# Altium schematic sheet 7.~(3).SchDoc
size 420 x 297 mm
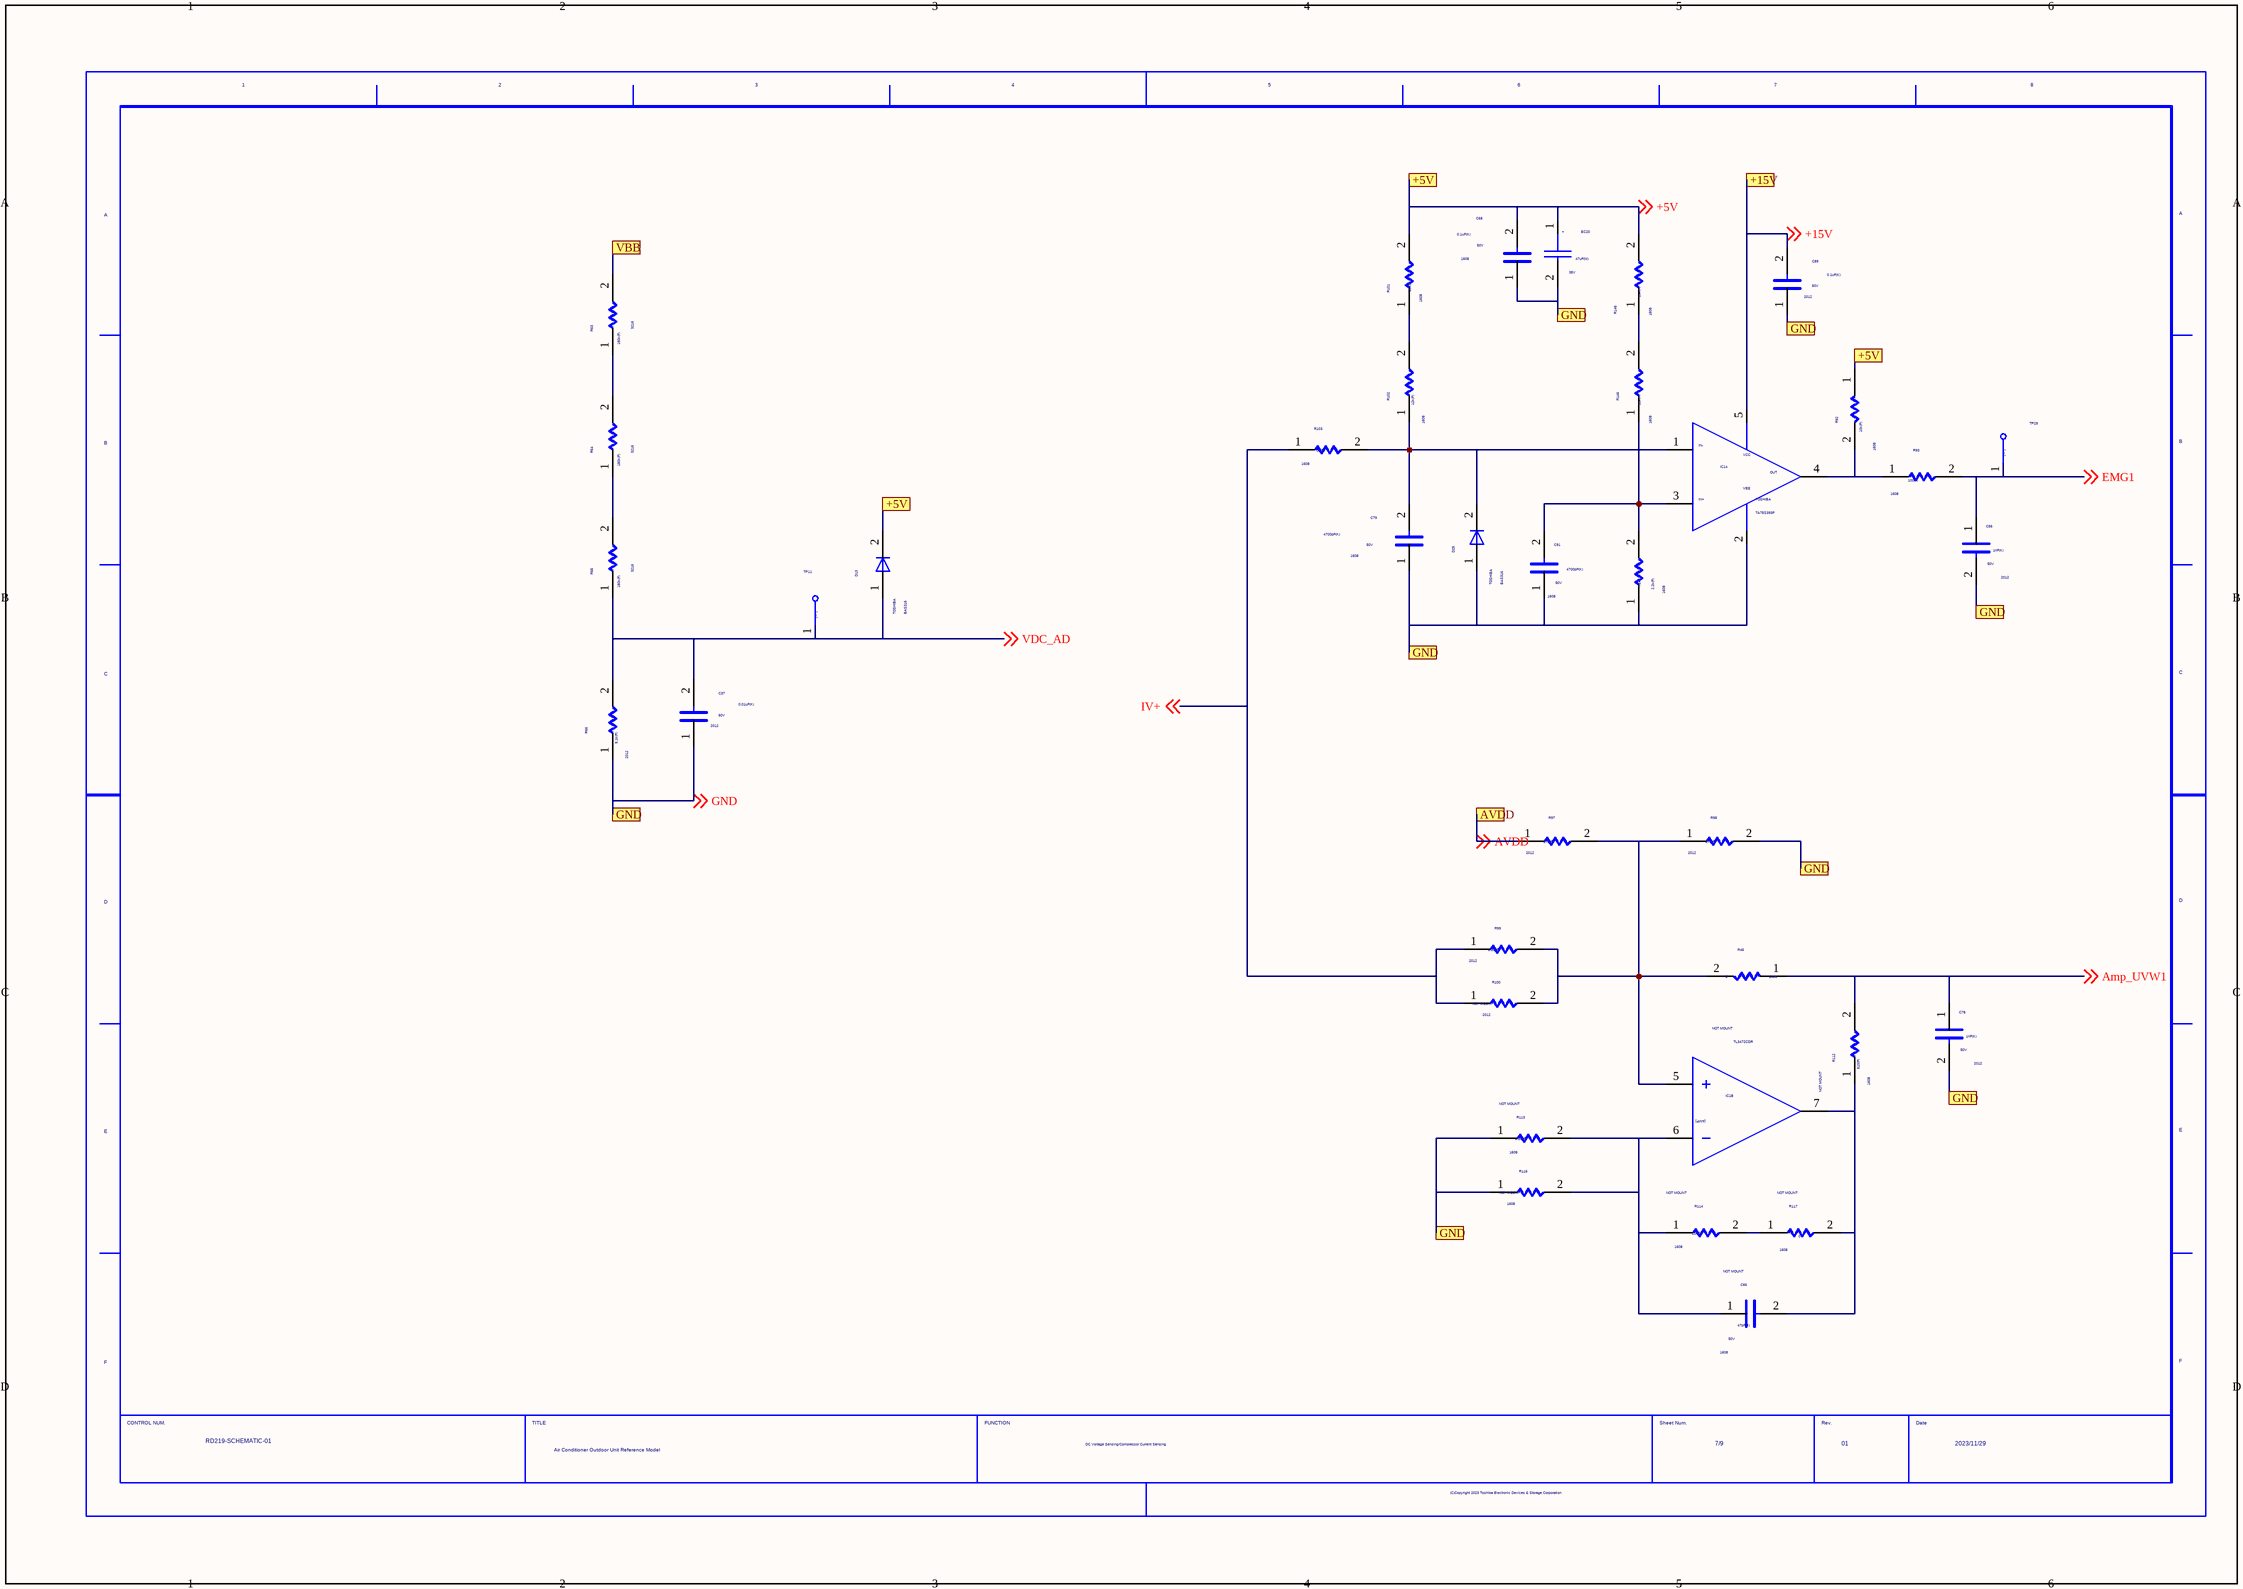
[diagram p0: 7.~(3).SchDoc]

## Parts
C37  SIZECODESMD: 2012  VAL2: 50V  VAL1: 0.01uF(K)  (hidden comment: C)
C56  VAL2: 50V  SIZECODESMD: 2012  VAL1: 1nF(K)  (hidden comment: C)
C66  NOTMOUNT: NOT MOUNT  VAL2: 50V  SIZECODESMD: 1608  VAL1: 47pF(J)  (hidden comment: C)
C68  VAL2: 50V  SIZECODESMD: 1608  VAL1: 0.1uF(K)  (hidden comment: C)
C78  VAL2: 50V  SIZECODESMD: 2012  VAL1: 1nF(K)  (hidden comment: C)
C79  VAL2: 50V  SIZECODESMD: 1608  VAL1: 4700pF(K)  (hidden comment: C)
C89  VAL2: 50V  SIZECODESMD: 2012  VAL1: 0.1uF(K)  (hidden comment: C)
C91  VAL2: 50V  SIZECODESMD: 1608  VAL1: 4700pF(K)  (hidden comment: C)
D13  USERCOMPTEXT3: TOSHIBA  VAL3: BAS316  (hidden comment: D_CUSTOM)
D25  USERCOMPTEXT3: TOSHIBA  VAL3: BAS316  (hidden comment: D_CUSTOM)
EC20  VAL2: 35V  VAL1: 47uF(M)  (hidden comment: EC)
IC1  NOTMOUNT: NOT MOUNT  VAL3: TL3472CDR  (hidden comment: AMP_1)  (part B of 2)
IC14  USERCOMPTEXT3: TOSHIBA  (hidden comment: TA75S393F)
R45  SIZECODESMD: 1608  VAL1: 0  (hidden comment: R)
R63  SIZECODESMD: 3216  VAL1: 180k(F)  (hidden comment: R)
R64  SIZECODESMD: 3216  VAL1: 180k(F)  (hidden comment: R)
R65  SIZECODESMD: 3216  VAL1: 180k(F)  (hidden comment: R)
R66  VAL1: 5.1k(F)  SIZECODESMD: 2012  (hidden comment: R)
R92  SIZECODESMD: 1608  VAL1: 10k(F)  (hidden comment: R)
R93  SIZECODESMD: 1608  VAL1: 100(F)  (hidden comment: R)
R97  SIZECODESMD: 2012  VAL1: 27k(F)  (hidden comment: R)
R98  SIZECODESMD: 2012  VAL1: 27k(F)  (hidden comment: R)
R99  SIZECODESMD: 2012  VAL1: 1.2k(F)  (hidden comment: R)
R100  SIZECODESMD: 2012  NOTMOUNT: NOT MOUNT  (hidden comment: R)
R101  SIZECODESMD: 1608  VAL1: 20k(F)  (hidden comment: R)
R102  SIZECODESMD: 1608  VAL1: 12k(F)  (hidden comment: R)
R103  SIZECODESMD: 1608  VAL1: 2k(F)  (hidden comment: R)
R112  NOTMOUNT: NOT MOUNT  SIZECODESMD: 1608  VAL1: 510(F)  (hidden comment: R)
R113  NOTMOUNT: NOT MOUNT  SIZECODESMD: 1608  VAL1: 1.1k(F)  (hidden comment: R)
R114  NOTMOUNT: NOT MOUNT  SIZECODESMD: 1608  VAL1: 12k(F)  (hidden comment: R)
R116  SIZECODESMD: 1608  NOTMOUNT: NOT MOUNT  (hidden comment: R)
R117  NOTMOUNT: NOT MOUNT  SIZECODESMD: 1608  VAL1: 0  (hidden comment: R)
R145  SIZECODESMD: 1608  VAL1: 10k(F)  (hidden comment: R)
R146  SIZECODESMD: 1608  VAL1: 12k(F)  (hidden comment: R)
R147  SIZECODESMD: 1608  VAL1: 2.2k(F)  (hidden comment: R)
TP11  TP  (value not drawn)
TP29  TP  (value not drawn)
U?  DATE: 2023/11/29  TITLE: Air Conditioner Outdoor Unit / Reference Model  FUNCTION: DC Voltage Sensing/Compressor Current Sensing  DRAWINGNUMBER: RD219-SCHEMATIC-01  SHEETNUMBER: 7/9  REVISION: 01  (hidden comment: WAKU_DEF100)

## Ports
+5V, +15V, AVDD, GND, VBB

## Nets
+5V: C68.2 D13.2 EC20.1 R92.1 R101.2 R145.2 ; off-sheet +5V, port +5V
+15V: C89.2 IC14.5 ; off-sheet +15V, port +15V
Amp_UVW1: C78.1 R45.1 R112.2 ; off-sheet Amp_UVW1
AVDD: R97.1 ; off-sheet AVDD, port AVDD
EMG1: C56.1 R93.2 TP29.1 ; off-sheet EMG1
GND: C37.1 C56.2 C68.1 C78.2 C79.1 C89.1 C91.1 D25.1 EC20.2 IC14.2 R66.1 R98.2 R113.1 R116.1 R147.1 ; off-sheet GND, port GND
IV+: R99.1 R100.1 R103.1 ; off-sheet IV+
NetC66_1: C66.1 IC1.6 R113.2 R114.1 R116.2
NetC66_2: C66.2 IC1.7 R112.1 R117.2
NetC79_2: C79.2 D25.2 IC14.1 R102.1 R103.2
NetC91_2: C91.2 IC14.3 R146.1 R147.2
NetIC1_5: IC1.5 R45.2 R97.2 R98.1 R99.2 R100.2
NetIC14_4: IC14.4 R92.2 R93.1
NetR63_1: R63.1 R64.2
NetR64_1: R64.1 R65.2
NetR101_1: R101.1 R102.2
NetR114_2: R114.2 R117.1
NetR145_1: R145.1 R146.2
VBB: R63.2 ; port VBB
VDC_AD: C37.2 D13.1 R65.1 R66.2 TP11.1 ; off-sheet VDC_AD

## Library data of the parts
C37 = C: OriginalSymbolOrigin: (2540,7620); VAL3: AC0805KRX7R9BB103
C56 C78 = C: OriginalSymbolOrigin: (2540,7620); COMP: AC0805KRX7R9BB102
C66 = C: OriginalSymbolOrigin: (2540,7620); COMP: AC0603JRNPO9BN470
C68 C89 = C: OriginalSymbolOrigin: (2540,7620); COMP: AC0603KRX7R9BB104
C79 C91 = C: OriginalSymbolOrigin: (2540,7620); COMP: AC0603KRX7R9BB472
D13 D25 = D_CUSTOM: SAVEAREA0: -1668,-97,14265,7829; SAVECOUNT: 4; TIME: 14:49:55; UPDATEUSER: w20165dm; UPDATETIME: 16:47:49; OriginalSymbolOrigin: (5080,5080)
EC20 = EC: SAVEAREA0: -1432,-1528,20311,14389; SAVECOUNT: 53; TIME: 15:02:55; UPDATEUSER: w20165dm; UPDATETIME: 16:35:05; OriginalSymbolOrigin: (2540,10160); VAL3: CS1V470M_CRE54
IC1 = AMP_1: SAVEAREA0: -6226,-235,36343,20943; TIME: 17:09:52; UPDATEUSER: w20165dm; SAVECOUNT: 1; OriginalSymbolOrigin: (5080,20320); CaptureCellPackProp: AMP_1B; FUNCN: IC1_2
IC14 = TA75S393F: SAVECOUNT: 22; SAVEAREA0: -11585,-294,41625,26178; TIME: 20:02:00; UPDATEUSER: w20165dm; UPDATETIME: 20:02:39; OriginalSymbolOrigin: (5080,22860)
R45 = R: OriginalSymbolOrigin: (5080,5080); COMP: AC0603FR_070RL; VAL3: AC0603FR-070RL; VAL2: 100mW
R63-R65 = R: OriginalSymbolOrigin: (5080,5080); VAL3: AC1206FR-07180KL; VAL2: 250mW; COMP: AC1206FR_07180KL
R66 = R: OriginalSymbolOrigin: (5080,5080); VAL3: AC0805FR-075K1L; VAL2: 125mW; COMP: AC0805FR_075K1L
R92 = R_Dup1: OriginalSymbolOrigin: (5080,5080); VAL2: 100mW; VAL3: AC0603FR_0710KL
R93 = R: OriginalSymbolOrigin: (5080,5080); COMP: AC0603FR_07100RL; VAL2: 100mW
R97 R98 = R: OriginalSymbolOrigin: (5080,5080); COMP: AC0805FR_0727KL; VAL2: 125mW
R99 = R: OriginalSymbolOrigin: (5080,5080); COMP: AC0805FR_071K2L; VAL2: 125mW
R100 = R: OriginalSymbolOrigin: (5080,5080); COMP: SMT_0805_R; VAL3: NC
R101 = R_Dup1: OriginalSymbolOrigin: (5080,5080); VAL3: AC0603FR_0720KL; VAL2: 100mW
R102 R146 = R_Dup1: OriginalSymbolOrigin: (5080,5080); VAL3: AC0603FR_0712KL; VAL2: 100mW
R103 = R: OriginalSymbolOrigin: (5080,5080); COMP: AC0603FR_072KL; VAL2: 100mW
R112 = R_Dup1: OriginalSymbolOrigin: (5080,5080); VAL2: 100mW; VAL3: AC0603FR_07510RL
R113 = R: OriginalSymbolOrigin: (5080,5080); COMP: AC0603FR_071K1L; VAL2: 100mW
R114 = R: OriginalSymbolOrigin: (5080,5080); COMP: AC0603FR_0712KL; VAL2: 100mW
R116 = R: OriginalSymbolOrigin: (5080,5080); COMP: SMT_0603_R
R117 = R: OriginalSymbolOrigin: (5080,5080); COMP: AC0603FR_070RL; VAL2: 100mW
R145 = R_Dup1: OriginalSymbolOrigin: (5080,5080); VAL3: AC0603FR_0710KL; VAL2: 100mW
R147 = R_Dup1: OriginalSymbolOrigin: (5080,5080); VAL3: AC0603FR_072K2L; VAL2: 100mW
TP11 = TP_Dup1: TIME: 16:12:21; UPDATEUSER: fukuda-y; UPDATETIME: 16:18:11; SAVECOUNT: 2; SAVEAREA0: -242,-92,12810,7836; OriginalSymbolOrigin: (0,7620); COMPCOMMENT: VDC_AD; VAL3: ZXD
TP29 = TP_Dup1: TIME: 16:12:21; UPDATEUSER: fukuda-y; UPDATETIME: 16:18:11; SAVECOUNT: 2; SAVEAREA0: -242,-92,12810,7836; OriginalSymbolOrigin: (0,7620); COMPCOMMENT: EMG1; VAL3: ZXD
U? = WAKU_DEF100: PLOTTIME: HH:MM; SAVEAREA0: -45080,-4508,463680,304612; TIME: 18:03:30; UPDATEUSER: sptcae13; UPDATETIME: 08:19:31; SAVECOUNT: 8; OriginalSymbolOrigin: (10160,284480)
